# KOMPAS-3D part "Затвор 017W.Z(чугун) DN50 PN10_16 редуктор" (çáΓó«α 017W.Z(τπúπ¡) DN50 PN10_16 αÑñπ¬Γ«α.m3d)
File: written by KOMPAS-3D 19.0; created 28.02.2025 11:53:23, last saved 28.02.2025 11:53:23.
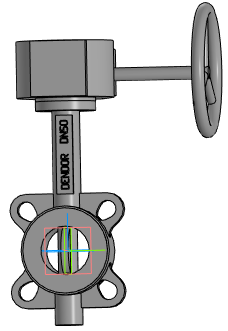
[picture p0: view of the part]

Document properties: Автор: Евгений; Полное имя файла: Затвор 017W.Z(чугун) DN50 PN10_16 редуктор.a3d

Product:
- Part/product: Затвор 017W.Z(чугун) DN50 PN10_16 редуктор
    Масса: 9.22522

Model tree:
1. Операция без истории:1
